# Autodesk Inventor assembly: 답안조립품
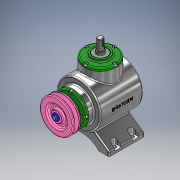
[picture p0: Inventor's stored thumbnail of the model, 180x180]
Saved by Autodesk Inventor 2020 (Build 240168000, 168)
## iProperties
Created: 2023-12
Part Number: 답안조립품
Document SubType Name: Weldment
Designer: 1강의실14
Weld Material: Welded Aluminum-6061
Author: 1강의실14
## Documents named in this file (17)
- C:\Users\1강의실14\Desktop\731203V1005\답안조립품.iam
- C:\Users\1강의실14\Desktop\731203V1005\본체.ipt
- C:\Users\1강의실14\Desktop\731203V1005\커버.ipt
- C:\Users\1강의실14\Desktop\731203V1005\베어링 6203.ipt
- C:\Users\1강의실14\Desktop\731203V1005\오일실 17 x 32 x 8.ipt
- C:\Users\1강의실14\Desktop\731203V1005\메인 축.ipt
- 메인 축.ipt
- C:\Users\1강의실14\Desktop\731203V1005\키 5 x 5 x 14.ipt
- C:\Users\1강의실14\Desktop\731203V1005\메인 베벨기어.ipt
- C:\Users\1강의실14\Desktop\731203V1005\서브 축.ipt
- 서브 축.ipt
- C:\Users\1강의실14\Desktop\731203V1005\키 4 x 4 x 14.ipt
- C:\Users\1강의실14\Desktop\731203V1005\서브 베벨기어.ipt
- C:\Users\1강의실14\Desktop\731203V1005\V-벨트풀리.ipt
- C:\Users\1강의실14\Desktop\731203V1005\볼트 M4 x 10.ipt
- C:\Users\1강의실14\Desktop\731203V1005\와셔 4 x 16.ipt
- C:\Users\1강의실14\Desktop\731203V1005\육각볼트 M4 x 8.ipt
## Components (1 placed, 1 different names)
1. V-벨트풀리:1 — 플러쉬:1
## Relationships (1: Flush 1)
- 플러쉬:1 [Flush]: V-벨트풀리:1
